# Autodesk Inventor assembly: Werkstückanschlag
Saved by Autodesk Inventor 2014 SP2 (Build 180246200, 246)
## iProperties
Created: 2015-07
Part Number: Werkstückanschlag
Document SubType Name: Assembly
Designer: e_krauts
Mass: 204.762 g
Surface Area: 785.53 cm^2
Volume: 204.762 cm^3
Density: 1 g/cm^3
Sending System: SolidWorks 2011
Last Author: e_boekem
Sachnummer: NWS 100-00-00
Author: e_krauts
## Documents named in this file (10)
- C:\SolidCAM_Temp\PRISMA IVCAM ZWISCHENSTAND1\Werkstückanschlag.iam
- C:\SolidCAM_Temp\PRISMA IVCAM ZWISCHENSTAND1\Seitenteil.ipt
- C:\SolidCAM_Temp\PRISMA IVCAM ZWISCHENSTAND1\Fuß.ipt
- C:\SolidCAM_Temp\PRISMA IVCAM ZWISCHENSTAND1\Bolzen.ipt
- C:\SolidCAM_Temp\PRISMA IVCAM ZWISCHENSTAND1\Bolzen_Bolzen mit Gewinde.ipt
- C:\SolidCAM_Temp\PRISMA IVCAM ZWISCHENSTAND1\Nadelhalterung.ipt
- C:\SolidCAM_Temp\PRISMA IVCAM ZWISCHENSTAND1\Nadelhalterung_Nadelhalterung Oberteil.ipt
- C:\SolidCAM_Temp\PRISMA IVCAM ZWISCHENSTAND1\Anschlagsnadel.ipt
- C:\SolidCAM_Temp\PRISMA IVCAM ZWISCHENSTAND1\Zylinderschraube ISO 4762 M8 x 55.ipt
- C:\SolidCAM_Temp\PRISMA IVCAM ZWISCHENSTAND1\Zylinderschraube ISO 10642 - M5 x 30.ipt
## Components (13 placed, 7 different names)
1. Seitenteil:1
2. Seitenteil:3
3. Fuß:1
4. Fuß:3
5. Bolzen:1
6. Bolzen:3
7. Nadelhalterung:1
8. Nadelhalterung:2
9. Anschlagsnadel:1
10. Zylinderschraube ISO 4762 M8 x 55:1
11. Zylinderschraube ISO 10642 - M5 x 30:1
12. Zylinderschraube ISO 4762 M8 x 55:2
13. Zylinderschraube ISO 10642 - M5 x 30:2
